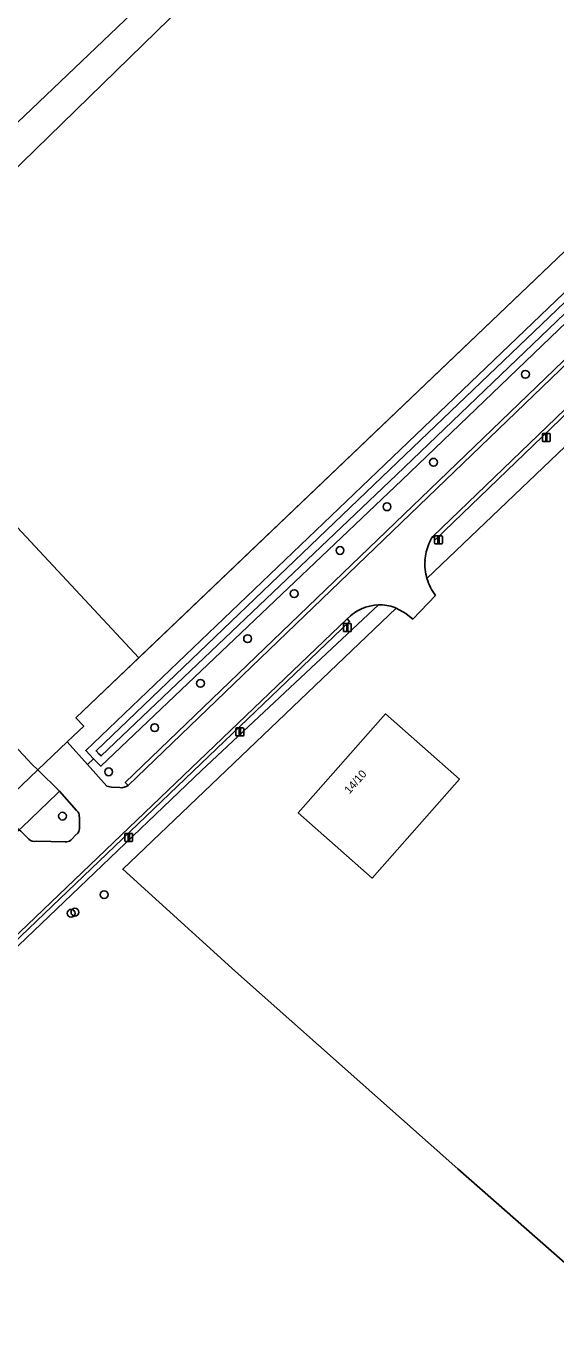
# Model space of a CAD drawing. Extents: x 157132 to 159279, y 384991 to 386650.
# Drawn here: x 157828.4 to 157894.6, y 385955.2 to 386118.1 of the extents above; entities that cross this region are included whole.
import ezdxf

# ---------------------------------------------------------------- set-up
doc = ezdxf.new("R2010")
doc.units = 0
for name, color, linetype in [('IMGEO_Boom', 7, 'Continuous'), ('IMGEO_Bouwland', 7, 'Continuous'), ('IMGEO_Erf', 7, 'Continuous'), ('IMGEO_Grasland_agrarisch', 7, 'Continuous'), ('IMGEO_Groenvoorziening', 7, 'Continuous'), ('IMGEO_Haag', 7, 'Continuous'), ('IMGEO_Hek', 7, 'Continuous'), ('IMGEO_Lichtmast', 7, 'Continuous'), ('IMGEO_Oever', 7, 'Continuous'), ('IMGEO_Pand', 7, 'Continuous'), ('IMGEO_Pand_nummerreeks', 7, 'Continuous'), ('IMGEO_Rijbaan_lokaal_open', 7, 'Continuous'), ('IMGEO_Waterloop', 7, 'Continuous')]:
    doc.layers.add(name, color=color, linetype=linetype)

msp = doc.modelspace()

# ---------------------------------------------------------------- linework, layer by layer
at = {"layer": 'IMGEO_Boom'}
for centre in [(157890.78, 386074.63), (157879.3, 386063.64), (157873.49, 386058.08), (157867.61, 386052.62), (157861.89, 386047.22), (157856.07, 386041.6), (157850.18, 386036.01), (157844.46, 386030.47), (157838.72, 386024.96), (157832.94, 386019.42), (157838.15, 386009.61), (157834.03, 386007.28), (157834.5, 386007.41)]:
    msp.add_circle(centre, 0.489, dxfattribs=at)
at = {"layer": 'IMGEO_Bouwland'}
msp.add_lwpolyline([(157907.89, 386100.62), (157908.11, 386103.25), (157909.47, 386103.17), (157972.32, 386163.18), (157975.23, 386165.96), (157973.79, 386167.47), (157936.15, 386206.72), (157933.34, 386204.01), (157921.22, 386191.28), (157874.85, 386146.92), (157824.5, 386097.81), (157804.71, 386079.73), (157842.48, 386039.2), (157906.64, 386100.46)], close=True, dxfattribs=at)
at = {"layer": 'IMGEO_Erf'}
for points in [[(157931.71, 386205.71), (157806.77, 386086.5), (157778.82, 386116.38), (157777.95, 386115.55), (157775.39, 386113.12), (157774.22, 386111.95), (157771.31, 386114.76), (157772.08, 386115.54), (157772.38, 386117.69), (157772.31, 386119.08)], [(157795.04, 386062.45), (157829.15, 386025.88), (157829.85, 386025.2), (157833.54, 386028.71), (157834.29, 386029.42), (157835.6, 386030.67), (157834.62, 386031.7), (157842.48, 386039.2), (157804.71, 386079.73), (157824.5, 386097.81), (157874.85, 386146.92), (157921.22, 386191.28)]]:
    msp.add_lwpolyline(points, dxfattribs=at)
at = {"layer": 'IMGEO_Grasland_agrarisch'}
msp.add_lwpolyline([(157908.63, 386215.04), (157898.31, 386225.94), (157896.14, 386228.23), (157778.82, 386116.38), (157806.77, 386086.5), (157931.71, 386205.71), (157917.17, 386220.94), (157912.61, 386216.91), (157917.18, 386212.42), (157913.9, 386209.47), (157914.39, 386208.98), (157910.06, 386204.6), (157907.66, 386207.24), (157909.29, 386208.84), (157907.66, 386210.54), (157910.44, 386213.13)], close=True, dxfattribs=at)
at = {"layer": 'IMGEO_Groenvoorziening'}
for points in [[(157841.16, 386023.24), (157840.78, 386023.62), (157877.74, 386059.18), (157921.03, 386100.83), (157958.38, 386136.76), (158006.36, 386183.22), (158048.9, 386224.14), (158243.2, 386409.3), (158244.83, 386411.77), (158245.36, 386411.41), (158254.46, 386424.63)], [(158252.27, 386422.97), (158247.48, 386416.73), (158244.19, 386412.89), (158243.62, 386413.14), (158143.52, 386317.82), (158000, 386180.76), (157977.11, 386158.17), (157941.94, 386124.54), (157921.52, 386105.73), (157916.5, 386100.92), (157918.67, 386099.84), (157916.45, 386097.68), (157914.49, 386098.99), (157875.32, 386061.42), (157837.74, 386025.65), (157836.83, 386026.59), (157836.07, 386025.87), (157838.49, 386023.17), (157839.07, 386023.03), (157840.1, 386022.98)], [(157878.48, 386049.1), (157923.9, 386092.49), (157925.82, 386094.62), (157923.61, 386095.67)], [(157923.02, 386095.83), (157879.56, 386053.99), (157879.21, 386054.36)], [(157923.9, 386092.49), (157878.48, 386049.1)], [(157823.82, 386021.18), (157824.59, 386020.36), (157824.76, 386020.51), (157824.84, 386020.42), (157829.85, 386025.2), (157829.15, 386025.88), (157795.04, 386062.45)], [(157879.56, 386046.98), (157876.7, 386044.05)], [(157804.36, 385981.2), (157807.42, 385984.13), (157850.3, 386025.12), (157872.43, 386045.82)], [(157872.43, 386045.82), (157850.3, 386025.12), (157807.42, 385984.13), (157804.36, 385981.2)], [(157882.35, 385975.36), (157854.58, 386000), (157840.47, 386012.79), (157874.62, 386045.41), (157874.46, 386045.51)], [(157874.62, 386045.41), (157840.47, 386012.79)], [(157876.7, 386044.05), (157875.82, 386044.76), (157874.62, 386045.41)], [(157868.51, 386044.07), (157868.81, 386043.75), (157825.77, 386002.54), (157806.71, 385984.19), (157804.48, 385982.22), (157791.24, 385971.51)], [(157834.71, 386020.11), (157832.57, 386022.52), (157832.28, 386022.24), (157827.9, 386018.05), (157827.55, 386017.72), (157827.74, 386017.54), (157828.72, 386016.55)], [(157835.06, 386017.88), (157835.05, 386019.34)], [(157833.97, 386016.42), (157834.71, 386017.16)], [(157829.7, 386016.28), (157833.28, 386016.21)], [(157840.47, 386012.79), (157854.58, 386000), (157882.35, 385975.36), (157921.45, 385940.96)], [(157750.58, 385919.79), (157748.18, 385918.41), (157746.48, 385917.53), (157748.39, 385916.43), (157748.86, 385916.17), (157748.99, 385916.39), (157749.19, 385916.71), (157801.31, 385887.35), (157869.06, 385848.74), (157892.38, 385889.57), (157921.45, 385940.96), (157882.35, 385975.36)]]:
    msp.add_lwpolyline(points, dxfattribs=at)
for points in [[(157836.83, 386026.59), (157835.85, 386027.6), (157873.22, 386063.38), (157912.1, 386100.6), (157911.57, 386100.96), (157907.89, 386100.62), (157906.64, 386100.46), (157842.48, 386039.2), (157834.62, 386031.7), (157835.6, 386030.67), (157834.29, 386029.42), (157833.54, 386028.71), (157836.07, 386025.87)], [(157882.55, 386024.03), (157871.62, 386011.68), (157862.39, 386019.85), (157873.32, 386032.2)], [(157824.84, 386020.42), (157826.94, 386018.3), (157827.55, 386017.72), (157827.9, 386018.05), (157832.28, 386022.24), (157832.57, 386022.52), (157829.85, 386025.2)]]:
    msp.add_lwpolyline(points, close=True, dxfattribs=at)
for centre, radius, start, end in [((157884.67, 386050.93), 6.46, 147.8859, 166.4468), ((157884.66, 386050.92), 6.44, 175.9863, 196.4282), ((157884.55, 386050.95), 6.33, 166.3795, 176.1926), ((157884.67, 386050.92), 6.45, 196.3579, 217.5705), ((157872.6, 386040.17), 5.65, 91.7167, 136.3331), ((157872.6, 386040.19), 5.63, 70.7164, 91.7616), ((157840.26, 386024.56), 1.59, 264.1729, 304.4078), ((157834.21, 386019.43), 0.841, 353.7428, 54.0444), ((157834.21, 386017.85), 0.851, 306.5085, 2.2303), ((157829.44, 386017.25), 1, 224.4818, 285.0279), ((157833.4, 386017.04), 0.847, 261.3852, 312.4045)]:
    msp.add_arc(centre, radius, start, end, dxfattribs=at)
at = {"layer": 'IMGEO_Haag'}
msp.add_lwpolyline([(157823.82, 386021.18), (157824.59, 386020.36), (157824.76, 386020.51), (157824.84, 386020.42), (157829.85, 386025.2), (157829.15, 386025.88), (157795.04, 386062.45)], dxfattribs=at)
at = {"layer": 'IMGEO_Hek'}
for points in [[(157906.64, 386100.46), (157834.62, 386031.7)], [(157923.9, 386092.49), (157878.48, 386049.1)], [(157874.62, 386045.41), (157840.47, 386012.79)], [(157834.62, 386031.7), (157835.6, 386030.67), (157834.29, 386029.42), (157833.54, 386028.71)], [(157833.54, 386028.71), (157829.85, 386025.2)], [(157829.85, 386025.2), (157824.84, 386020.42)], [(157840.47, 386012.79), (157854.58, 386000), (157882.35, 385975.36), (157921.45, 385940.96)]]:
    msp.add_lwpolyline(points, dxfattribs=at)
at = {"layer": 'IMGEO_Lichtmast'}
for p, q in [((157893, 386067.23), (157893.79, 386067.23)), ((157893.79, 386067.23), (157893, 386067.23)), ((157892.9, 386066.34), (157892.9, 386067.13)), ((157892.9, 386067.13), (157892.9, 386066.34)), ((157893.79, 386066.24), (157893, 386066.24)), ((157893, 386066.24), (157893.79, 386066.24)), ((157893.89, 386067.13), (157893.89, 386066.34)), ((157893.89, 386066.34), (157893.89, 386067.13)), ((157879.43, 386053.54), (157879.43, 386054.33)), ((157879.43, 386054.33), (157879.43, 386053.54)), ((157879.53, 386054.43), (157880.32, 386054.43)), ((157880.32, 386054.43), (157879.53, 386054.43)), ((157880.42, 386054.33), (157880.42, 386053.54)), ((157880.42, 386053.54), (157880.42, 386054.33)), ((157880.32, 386053.44), (157879.53, 386053.44)), ((157879.53, 386053.44), (157880.32, 386053.44)), ((157868.04, 386042.58), (157868.04, 386043.38)), ((157868.04, 386043.38), (157868.04, 386042.58)), ((157868.14, 386043.48), (157868.93, 386043.48)), ((157868.93, 386043.48), (157868.14, 386043.48)), ((157869.03, 386043.38), (157869.03, 386042.58)), ((157869.03, 386042.58), (157869.03, 386043.38)), ((157868.93, 386042.48), (157868.14, 386042.48)), ((157868.14, 386042.48), (157868.93, 386042.48)), ((157854.61, 386029.54), (157854.61, 386030.34)), ((157854.61, 386030.34), (157854.61, 386029.54)), ((157854.71, 386030.44), (157855.5, 386030.44)), ((157855.5, 386030.44), (157854.71, 386030.44)), ((157855.6, 386030.34), (157855.6, 386029.54)), ((157855.6, 386029.54), (157855.6, 386030.34)), ((157855.5, 386029.44), (157854.71, 386029.44)), ((157854.71, 386029.44), (157855.5, 386029.44)), ((157840.73, 386016.36), (157840.73, 386017.16)), ((157840.73, 386017.16), (157840.73, 386016.36)), ((157840.83, 386017.26), (157841.61, 386017.26)), ((157841.61, 386017.26), (157840.83, 386017.26)), ((157841.71, 386017.16), (157841.71, 386016.36)), ((157841.71, 386016.36), (157841.71, 386017.16)), ((157841.61, 386016.26), (157840.83, 386016.26)), ((157840.83, 386016.26), (157841.61, 386016.26))]:
    msp.add_line(p, q, dxfattribs=at)
for points in [[(157893.32, 386067.11), (157893.47, 386067.11), (157893.47, 386066.36), (157893.32, 386066.36), (157893.32, 386067.11)], [(157879.85, 386054.31), (157880, 386054.31), (157880, 386053.56), (157879.85, 386053.56), (157879.85, 386054.31)], [(157868.46, 386043.35), (157868.61, 386043.35), (157868.61, 386042.6), (157868.46, 386042.6), (157868.46, 386043.35)], [(157855.03, 386030.31), (157855.18, 386030.31), (157855.18, 386029.56), (157855.03, 386029.56), (157855.03, 386030.31)], [(157841.14, 386017.13), (157841.3, 386017.13), (157841.3, 386016.38), (157841.14, 386016.38), (157841.14, 386017.13)]]:
    msp.add_lwpolyline(points, dxfattribs=at)
for centre, start, end in [((157893, 386067.13), 90, 180), ((157893, 386067.13), 90, 180), ((157893.79, 386067.13), 0, 90), ((157893.79, 386067.13), 360, 90), ((157893, 386066.34), 180, 270), ((157893, 386066.34), 180, 270), ((157893.79, 386066.34), 270, 0), ((157893.79, 386066.34), 270, 0), ((157879.53, 386054.33), 90, 180), ((157879.53, 386054.33), 90, 180), ((157880.32, 386054.33), 0, 90), ((157880.32, 386054.33), 360, 90), ((157879.53, 386053.54), 180, 270), ((157879.53, 386053.54), 180, 270), ((157880.32, 386053.54), 270, 0), ((157880.32, 386053.54), 270, 0), ((157868.14, 386043.38), 90, 180), ((157868.14, 386043.38), 90, 180), ((157868.93, 386043.38), 0, 90), ((157868.93, 386043.38), 360, 90), ((157868.14, 386042.58), 180, 270), ((157868.14, 386042.58), 180, 270), ((157868.93, 386042.58), 270, 0), ((157868.93, 386042.58), 270, 0), ((157854.71, 386030.34), 90, 180), ((157854.71, 386030.34), 90, 180), ((157855.5, 386030.34), 0, 90), ((157855.5, 386030.34), 360, 90), ((157854.71, 386029.54), 180, 270), ((157854.71, 386029.54), 180, 270), ((157855.5, 386029.54), 270, 0), ((157855.5, 386029.54), 270, 0), ((157840.83, 386017.16), 90, 180), ((157840.83, 386017.16), 90, 180), ((157841.61, 386017.16), 0, 90), ((157841.61, 386017.16), 360, 90), ((157840.83, 386016.36), 180, 270), ((157840.83, 386016.36), 180, 270), ((157841.61, 386016.36), 270, 0), ((157841.61, 386016.36), 270, 0)]:
    msp.add_arc(centre, 0.1, start, end, dxfattribs=at)
at = {"layer": 'IMGEO_Oever'}
for points in [[(158247.69, 386422.99), (158244.91, 386419.57), (158240.69, 386415.19), (158240.57, 386415.07), (157913.82, 386102.24), (157912.1, 386100.6), (157873.22, 386063.38), (157835.85, 386027.6), (157836.83, 386026.59), (157837.74, 386025.65), (157875.32, 386061.42), (157914.49, 386098.99), (157916.5, 386100.92), (157921.52, 386105.73), (157941.94, 386124.54), (157977.11, 386158.17), (158000, 386180.76), (158143.52, 386317.82), (158243.62, 386413.14), (158244.19, 386412.89), (158247.48, 386416.73), (158252.27, 386422.97)], [(158142.89, 386318.48), (157999.36, 386181.41), (157976.47, 386158.82), (157941.32, 386125.21), (157920.89, 386106.4), (157915.86, 386101.58), (157915.63, 386101.35), (157913.86, 386099.65), (157913.72, 386099.52), (157874.69, 386062.08), (157837.76, 386026.94), (157837.48, 386027.22), (157837.14, 386027.57), (157873.85, 386062.72), (157912.73, 386099.94), (157912.88, 386100.08), (157914.45, 386101.59), (157914.69, 386101.81), (158241.2, 386414.41)]]:
    msp.add_lwpolyline(points, dxfattribs=at)
at = {"layer": 'IMGEO_Pand'}
msp.add_lwpolyline([(157882.55, 386024.03), (157873.32, 386032.2), (157862.39, 386019.85), (157871.62, 386011.68)], close=True, dxfattribs=at)
at = {"layer": 'IMGEO_Rijbaan_lokaal_open'}
for points in [[(157921.53, 386100.59), (157921.03, 386100.83), (157877.74, 386059.18), (157840.78, 386023.62), (157841.16, 386023.24)], [(157923.02, 386095.83), (157925.85, 386098.55), (157925.37, 386098.78), (157879.21, 386054.36), (157879.56, 386053.99)]]:
    msp.add_lwpolyline(points, close=True, dxfattribs=at)
for points in [[(157925.37, 386098.78), (157921.53, 386100.59), (157841.16, 386023.24)], [(157879.21, 386054.36), (157925.37, 386098.78)], [(157874.46, 386045.51), (157874.62, 386045.41), (157875.82, 386044.76), (157876.7, 386044.05), (157879.56, 386046.98)], [(157791.24, 385971.51), (157804.48, 385982.22), (157806.71, 385984.19), (157825.77, 386002.54), (157868.81, 386043.75), (157868.51, 386044.07), (157807.12, 385985.32), (157804.17, 385982.59), (157790.9, 385971.9)], [(157790.9, 385971.9), (157804.17, 385982.59), (157807.12, 385985.32), (157868.51, 386044.07)], [(157840.1, 386022.98), (157839.07, 386023.03), (157838.49, 386023.17), (157836.07, 386025.87), (157833.54, 386028.71), (157829.85, 386025.2), (157832.57, 386022.52), (157834.71, 386020.11)], [(157835.05, 386019.34), (157835.06, 386017.88)], [(157828.72, 386016.55), (157827.74, 386017.54), (157827.55, 386017.72), (157822.07, 386012.48), (157822.26, 386012.29), (157822.59, 386011.94)], [(157834.71, 386017.16), (157833.97, 386016.42)], [(157833.28, 386016.21), (157829.7, 386016.28)]]:
    msp.add_lwpolyline(points, dxfattribs=at)
for centre, radius, start, end in [((157884.67, 386050.93), 6.46, 147.8859, 166.4468), ((157884.66, 386050.92), 6.44, 175.9863, 196.4282), ((157884.55, 386050.95), 6.33, 166.3795, 176.1926), ((157884.67, 386050.92), 6.45, 196.3579, 217.5705), ((157872.6, 386040.17), 5.65, 91.7167, 136.3331), ((157872.6, 386040.19), 5.63, 70.7164, 91.7616), ((157840.26, 386024.56), 1.59, 264.1729, 304.4078), ((157834.21, 386019.43), 0.841, 353.7428, 54.0444), ((157834.21, 386017.85), 0.851, 306.5085, 2.2303), ((157829.44, 386017.25), 1, 224.4818, 285.0279), ((157833.4, 386017.04), 0.847, 261.3852, 312.4045)]:
    msp.add_arc(centre, radius, start, end, dxfattribs=at)
at = {"layer": 'IMGEO_Waterloop'}
msp.add_lwpolyline([(158241.2, 386414.41), (157914.69, 386101.81), (157914.45, 386101.59), (157912.88, 386100.08), (157912.73, 386099.94), (157873.85, 386062.72), (157837.14, 386027.57), (157837.48, 386027.22), (157837.76, 386026.94), (157874.69, 386062.08), (157913.72, 386099.52), (157913.86, 386099.65), (157915.63, 386101.35), (157915.86, 386101.58), (157920.89, 386106.4), (157941.32, 386125.21), (157976.47, 386158.82), (157999.36, 386181.41), (158142.89, 386318.48)], dxfattribs=at)

# ---------------------------------------------------------------- texts
at = {"layer": 'IMGEO_Pand_nummerreeks'}
msp.add_text('14/10', height=1, rotation=48.5298, dxfattribs=at).set_placement((157868.8, 386022.13))

doc.saveas('drawing.dxf')
